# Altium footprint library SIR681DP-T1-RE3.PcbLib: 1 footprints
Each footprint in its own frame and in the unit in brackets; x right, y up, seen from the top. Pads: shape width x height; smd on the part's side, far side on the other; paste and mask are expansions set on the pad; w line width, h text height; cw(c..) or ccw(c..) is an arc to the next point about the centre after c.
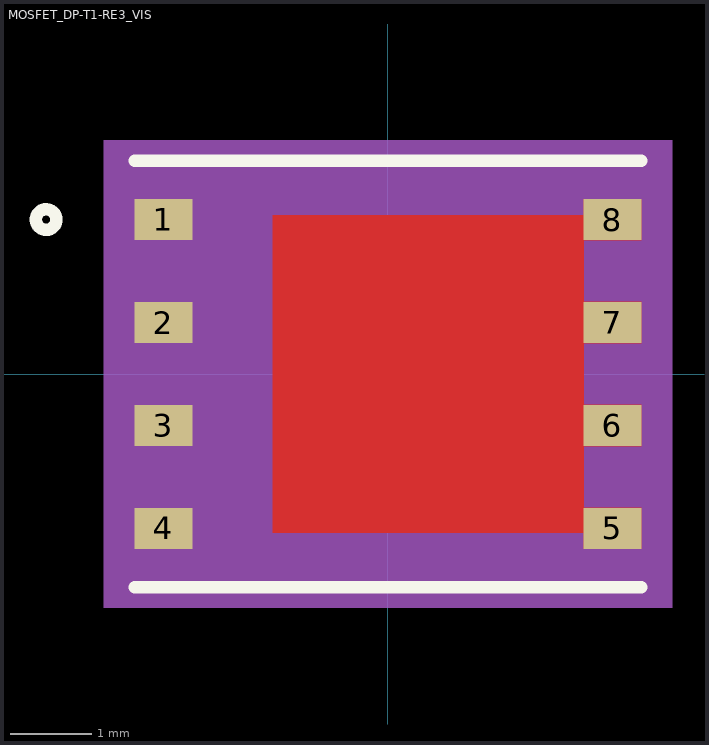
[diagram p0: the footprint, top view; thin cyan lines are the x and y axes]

## MOSFET_DP-T1-RE3_VIS [mil]
pads (8):
  rect 28x20 smd paste-10 mask+0: 1(-109.06,75) 2(-109.06,25) 3(-109.06,-25) 4(-109.06,-75) 5(109.06,-75) 6(109.06,-25) 7(109.06,25) 8(109.06,75)
Top Layer:
  region: 0,77
  region: 0,-77
  region: -55.95,77 95.06,77 95.06,85 123.06,85 123.06,65 95.06,65 95.06,35 123.06,35 123.06,15 95.06,15 95.06,-15 123.06,-15 123.06,-35 95.06,-35 95.06,-65 123.06,-65 123.06,-85 95.06,-85 95.06,-77 -55.95,-77
Top Overlay:
  circle w6: c-166.06,75 r5
  lines w6: -123,-103.5 123,-103.5 ; -123,103.5 123,103.5
Top Paste:
  region: -29.1,73.06 -71.56,73.06 -71.56,29.6 -29.1,29.6
  region: -29.1,21.73 -71.56,21.73 -71.56,-21.73 -29.1,-21.73
  region: -29.1,-29.6 -71.56,-29.6 -71.56,-73.06 -29.1,-73.06
  region: 21.23,73.06 -21.23,73.06 -21.23,29.6 21.23,29.6
  region: 21.23,21.73 -21.23,21.73 -21.23,-21.73 21.23,-21.73
  region: 21.23,-29.6 -21.23,-29.6 -21.23,-73.06 21.23,-73.06
  region: 71.56,73.06 29.1,73.06 29.1,29.6 71.56,29.6
  region: 71.56,21.73 29.1,21.73 29.1,-21.73 71.56,-21.73
  region: 71.56,-29.6 29.1,-29.6 29.1,-73.06 71.56,-73.06
  region: -55.95,-77 -55.95,77 95.06,77 95.06,85 123.06,85 123.06,65 95.06,65 95.06,35 123.06,35 123.06,15 95.06,15 95.06,-15 123.06,-15 123.06,-35 95.06,-35 95.06,-65 123.06,-65 123.06,-85 95.06,-85 95.06,-77
Top Solder:
  region: 0,77
  region: 0,-77
  region: -55.95,-77 -55.95,77 95.06,77 95.06,85 123.06,85 123.06,65 95.06,65 95.06,35 123.06,35 123.06,15 95.06,15 95.06,-15 123.06,-15 123.06,-35 95.06,-35 95.06,-65 123.06,-65 123.06,-85 95.06,-85 95.06,-77
Mechanical 5:
  region: 138.06,-113.5 -138.06,-113.5 -138.06,113.5 138.06,113.5
Mechanical 13:
  circle w0: c-95.06,75 r3
  lines w0: -12,98.5 ccw(c0,98.5) 12,98.5
  lines w1: -118,-98.5 118,-98.5 118,98.5 -118,98.5 -118,-98.5
Mechanical 15:
  region: -128,-95 -133.06,-95 -133.06,95 -128,95 -128,108.5 128,108.5 128,95 133.06,95 133.06,-95 128,-95 128,-108.5 -128,-108.5
  lines w6: -133.06,-95 -133.06,95 -128,95 -128,108.5 128,108.5 128,95 133.06,95 133.06,-95 128,-95 128,-108.5 -128,-108.5 -128,-95 -133.06,-95
3D body: height 10, standoff 0, extent 0,0 10,10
